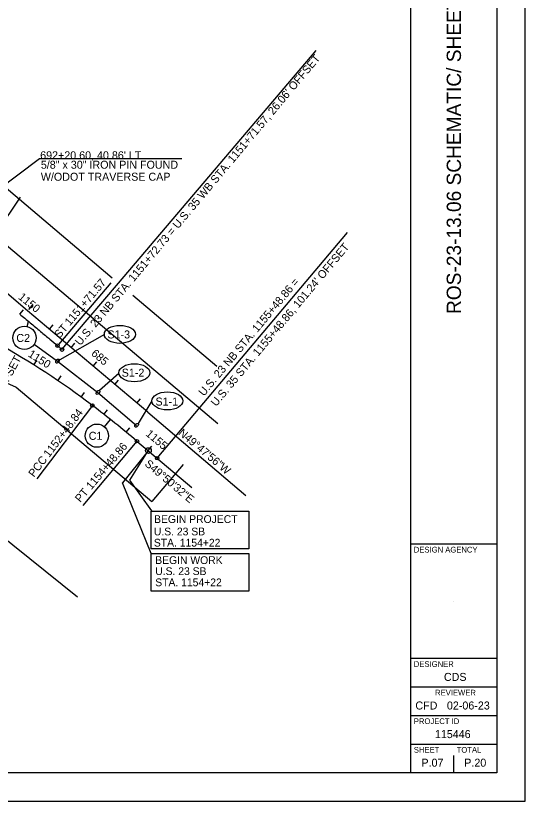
# Model space of a CAD drawing. Extents: x 310 to 1844719, y 48 to 494239.
# Drawn here: x 1838467 to 1840250, y 489839 to 492586 of the extents above; entities that cross this region are included whole.
import ezdxf

# ---------------------------------------------------------------- set-up
doc = ezdxf.new("R2010")
doc.units = 0
for name, color, linetype in [('6ft clearance', 7, 'Continuous'), ('Clear Zones 30ft', 7, 'Continuous'), ('Default', 7, 'Continuous'), ('Geohazard Areas', 7, 'Continuous'), ('Guardrail', 7, 'Continuous'), ('LT_P_Control_Center', 7, 'Continuous'), ('LT_P_PullBox', 7, 'Continuous'), ('PV_X_Curb', 7, 'Continuous'), ('PV_X_EOP', 7, 'Continuous'), ('RW_X_CL_100_Stations', 7, 'Continuous'), ('RW_X_Esmt_LA', 7, 'Continuous'), ('Shoulder lines', 7, 'Continuous'), ('Traffic Sign', 7, 'Continuous')]:
    doc.layers.add(name, color=color, linetype=linetype)

msp = doc.modelspace()

# ---------------------------------------------------------------- linework, layer by layer
at = {"layer": '6ft clearance'}
msp.add_line((1838613.1, 491432), (1838614, 491431.3), dxfattribs=at)
at = {"layer": 'Clear Zones 30ft'}
for p, q in [((1839849.7, 489938.7), (1839849.7, 494138.7)), ((1839849.7, 490738.7), (1840149.7, 490738.7)), ((1839849.7, 490338.7), (1840149.7, 490338.7)), ((1839849.7, 490238.7), (1840149.7, 490238.7)), ((1839849.7, 490138.7), (1840149.7, 490138.7)), ((1839849.7, 490038.7), (1840149.7, 490038.7))]:
    msp.add_line(p, q, dxfattribs=at)
msp.add_lwpolyline([(1833749.7, 494138.7), (1840149.7, 494138.7), (1840149.7, 489938.7), (1833749.7, 489938.7)], close=True, dxfattribs=at)
at = {"layer": 'Default'}
for p, q in [((1838100.7, 492265.5), (1838804.8, 491669.7)), ((1838508.4, 491554.1), (1838254.8, 491768.4)), ((1838876.3, 491609.2), (1839170.1, 491360.6)), ((1838928.5, 491199.1), (1838508.4, 491554.1)), ((1837590, 491431.3), (1838683, 490553.9)), ((1838928.5, 491199.1), (1839272.2, 490908.6)), ((1838891.1, 491098), (1839083.3, 490935.9))]:
    msp.add_line(p, q, dxfattribs=at)
for centre, radius, start, end in [((1837004.6, 488939.8), 2864.8, 52.8425, 60.8195), ((1836427.8, 488178.7), 3819.7, 49.8425, 52.8426)]:
    msp.add_arc(centre, radius, start, end, dxfattribs=at)
msp.add_open_spline([(1838481.3, 491541.8), (1838491.2, 491533.8), (1838518.3, 491511.6), (1838553.7, 491482.1), (1838587.7, 491453.5), (1838604.6, 491439.2), (1838613.1, 491432)], degree=3, dxfattribs=at)
at = {"layer": 'Geohazard Areas'}
for p, q in [((1839999.7, 490538.7), (1839999.7, 490538.7)), ((1839999.7, 489938.7), (1839999.7, 489998.7)), ((1839924.7, 489973.7), (1839924.7, 489973.7))]:
    msp.add_line(p, q, dxfattribs=at)
at = {"layer": 'LT_P_Control_Center'}
for centre, major_axis in [((1838613, 491378.2), (-4.37, -6.7)), ((1838754.4, 491268.6), (-5.08, -6.18)), ((1838889.6, 491153.5), (-5.25, -6.04))]:
    msp.add_ellipse(centre, major_axis=major_axis, ratio=0.625, dxfattribs=at)
at = {"layer": 'LT_P_PullBox'}
for p, q in [((1838531.4, 491437.3), (1838613, 491378.2)), ((1838613, 491378.2), (1838754.4, 491268.6)), ((1838754.4, 491268.6), (1838889.6, 491153.5))]:
    msp.add_line(p, q, dxfattribs=at)
at = {"layer": 'PV_X_Curb'}
for p, q in [((1838256.8, 491932.4), (1839173.6, 491159.8)), ((1837774.1, 491590.8), (1838467.8, 491287.1)), ((1838467.8, 491287.1), (1838943.2, 490886.6)), ((1839052.9, 491016.4), (1838943.2, 490886.6))]:
    msp.add_line(p, q, dxfattribs=at)
at = {"layer": 'PV_X_EOP'}
for p, q in [((1838481.3, 491541.8), (1838493.9, 491557.4)), ((1838512.3, 491558.7), (1838525.2, 491574)), ((1838584.8, 491489.5), (1838597.7, 491504.8)), ((1838661.2, 491425), (1838674.1, 491440.3)), ((1838530.3, 491364.5), (1838541, 491381.4)), ((1838737.5, 491360.5), (1838750.5, 491375.7)), ((1838614, 491309.7), (1838625.3, 491326.3)), ((1838813.9, 491295.9), (1838826.8, 491311.2)), ((1838695.8, 491252.1), (1838707.6, 491268.3)), ((1838890.3, 491231.4), (1838903.2, 491246.6)), ((1838775.5, 491191.8), (1838787.8, 491207.6)), ((1838853.6, 491129.3), (1838866.3, 491144.8)), ((1838930.2, 491065.1), (1838943.1, 491080.3))]:
    msp.add_line(p, q, dxfattribs=at)
at = {"layer": 'RW_X_CL_100_Stations'}
for p, q in [((1838826.4, 491650.9), (1839517.7, 492464.2)), ((1838961.7, 491038.5), (1839628.2, 491828.3)), ((1838628.7, 491418.3), (1838826.4, 491650.9)), ((1838613, 491432.2), (1838628.7, 491418.3))]:
    msp.add_line(p, q, dxfattribs=at)
at = {"layer": 'RW_X_Esmt_LA'}
msp.add_lwpolyline([(1833449.7, 489838.7), (1840249.7, 489838.7), (1840249.7, 494238.7), (1833449.7, 494238.7)], close=True, dxfattribs=at)
at = {"layer": 'Shoulder lines'}
for p, q in [((1838160.8, 491794.4), (1838550.1, 492087.1)), ((1838550.1, 492087.1), (1839048, 492087.1)), ((1838776.9, 491471.7), (1838613, 491378.2)), ((1838827.7, 491334.6), (1838759.4, 491274.8)), ((1838942.9, 491238.9), (1838894.8, 491159.5)), ((1838930.1, 491064.2), (1838840.2, 490953)), ((1838941.1, 490705.8), (1838840.2, 490953))]:
    msp.add_line(p, q, dxfattribs=at)
msp.add_lwpolyline([(1838943.3, 490854), (1838865.7, 490961.3), (1838930.6, 491064.7)], dxfattribs=at)
for points in [[(1838941.2, 490853.7), (1839282.9, 490853.7), (1839282.9, 490722), (1838941.2, 490722)], [(1838940.7, 490705.5), (1839282.4, 490705.5), (1839282.4, 490573.9), (1838940.7, 490573.9)]]:
    msp.add_lwpolyline(points, close=True, dxfattribs=at)
msp.add_circle((1838931, 491065.3), 10, dxfattribs=at)
for centre in [(1838831.3, 491471.7), (1838881.9, 491337.3), (1838997.3, 491238.9)]:
    msp.add_ellipse(centre, major_axis=(-54.4, 0), ratio=0.57803, dxfattribs=at)
at = {"layer": 'Traffic Sign'}
for p, q in [((1838298.8, 491679), (1838483.3, 491951.1)), ((1838617.9, 491435.9), (1838800.4, 491652.1)), ((1838507.4, 491498.8), (1838512, 491516.7)), ((1838734.9, 491223), (1838540.4, 490966.3)), ((1838797.6, 491174.4), (1838776.5, 491148.7)), ((1838891.1, 491098), (1838701.7, 490873.6))]:
    msp.add_line(p, q, dxfattribs=at)
for centre, radius in [((1838497.4, 491459.5), 40.6), ((1838613.1, 491432), 6), ((1838628.7, 491418.3), 6), ((1838734.9, 491223), 6), ((1838750.7, 491117.3), 40.6), ((1838891.1, 491098), 6), ((1838961.7, 491038.5), 6)]:
    msp.add_circle(centre, radius, dxfattribs=at)

# ---------------------------------------------------------------- texts
at = {"layer": 'Geohazard Areas'}
msp.add_text('ROS-23-13.06 SCHEMATIC/ SHEET INDEX', height=50, rotation=90, dxfattribs=at).set_placement((1840024.7, 491542.8))
for s, height, p in [('DESIGN AGENCY', 20, (1839859.7, 490708.7)), ('DESIGNER', 20, (1839859.7, 490308.7)), ('CDS', 28, (1839965, 490259.7)), ('REVIEWER', 20, (1839934.1, 490208.7)), ('CFD', 28, (1839865.2, 490159.7)), ('02-06-23', 28, (1839975.5, 490159.7)), ('PROJECT ID', 20, (1839859.7, 490108.7)), ('115446', 28, (1839933.5, 490059.7)), ('SHEET', 20, (1839859.7, 490008.7)), ('TOTAL', 20, (1840009.7, 490008.7)), ('P.07', 28, (1839886.4, 489959.7)), ('P.20', 28, (1840036.2, 489959.7))]:
    msp.add_text(s, height=height, dxfattribs=at).set_placement(p)
at = {"layer": 'Guardrail'}
for s, rotation, p in [('N49°47\'56"W', 319.7988, (1839033.8, 491123.2)), ('S49°50\'32"E', 319.8425, (1838915.7, 491015))]:
    msp.add_text(s, height=28, rotation=rotation, dxfattribs=at).set_placement(p)
at = {"layer": 'PV_X_EOP'}
for s, rotation, p in [("692+20.60, 40.86' LT.", 0.0079, (1838552.4, 492083.9)), ('5/8" x 30" IRON PIN FOUND ', 0.0079, (1838554.7, 492050.9)), ('W/ODOT TRAVERSE CAP', 0.0079, (1838554.7, 492008.9)), ('1150', 327.8194, (1838507.7, 491395.9)), ('685', 319.7988, (1838728.8, 491401.2)), ('1155', 319.8425, (1838919.5, 491120))]:
    msp.add_text(s, height=28, rotation=rotation, dxfattribs=at).set_placement(p)
at = {"layer": 'RW_X_CL_100_Stations'}
for s, rotation, p in [("U.S. 23 NB STA. 1151+72.73 = U.S. 35 WB STA. 1151+71.57, 26.06' OFFSET", 50.0756, (1838692.8, 491430.3)), ("U.S. 35 STA. 1155+48.86, 101.24' OFFSET ", 50.0756, (1839168.1, 491217.4)), ('U.S. 23 NB STA. 1155+48.86 = ', 50.0756, (1839125.2, 491253.4)), ("U.S. 23 SB STA. 32+90.98 = U.S. 35 EB STA. 32+90.98, 25.14' OFFSET ", 61.2354, (1837902.8, 490321.8))]:
    msp.add_text(s, height=28, rotation=rotation, dxfattribs=at).set_placement(p)
at = {"layer": 'Shoulder lines'}
for s, height, p in [('C2', 28, (1838469, 491445)), ('S1-3', 28, (1838787.7, 491457.4)), ('S1-2', 28, (1838837.7, 491323.6)), ('S1-1', 28, (1838955.9, 491222.7)), ('BEGIN PROJECT', 27.104, (1838950.9, 490812)), ('U.S. 23 SB', 27.1, (1838950.2, 490768.7)), ('STA. 1154+22', 27.104, (1838950.2, 490729.5)), ('BEGIN WORK', 27.1, (1838955, 490668.6)), ('U.S. 23 SB', 27.1, (1838955, 490630)), ('STA. 1154+22', 27.104, (1838955, 490590.8))]:
    msp.add_text(s, height=height, dxfattribs=at).set_placement(p)
at = {"layer": 'Traffic Sign'}
for s, rotation, p in [('1151+71.57', 49.8426, (1838656.5, 491499.7)), ('1150', 320.9465, (1838473.7, 491598)), ('ST', 49.8426, (1838620.5, 491456)), ('1152+48.84', 52.8426, (1838583.7, 491039.2)), ('1154+48.86', 49.8425, (1838731.4, 490926.6)), ('PCC', 52.8426, (1838530.9, 490970)), ('PT', 49.8425, (1838692.8, 490881.9))]:
    msp.add_text(s, height=28, rotation=rotation, dxfattribs=at).set_placement(p)
msp.add_text('C1', height=28, dxfattribs=at).set_placement((1838722.3, 491102.9))

doc.saveas('drawing.dxf')
